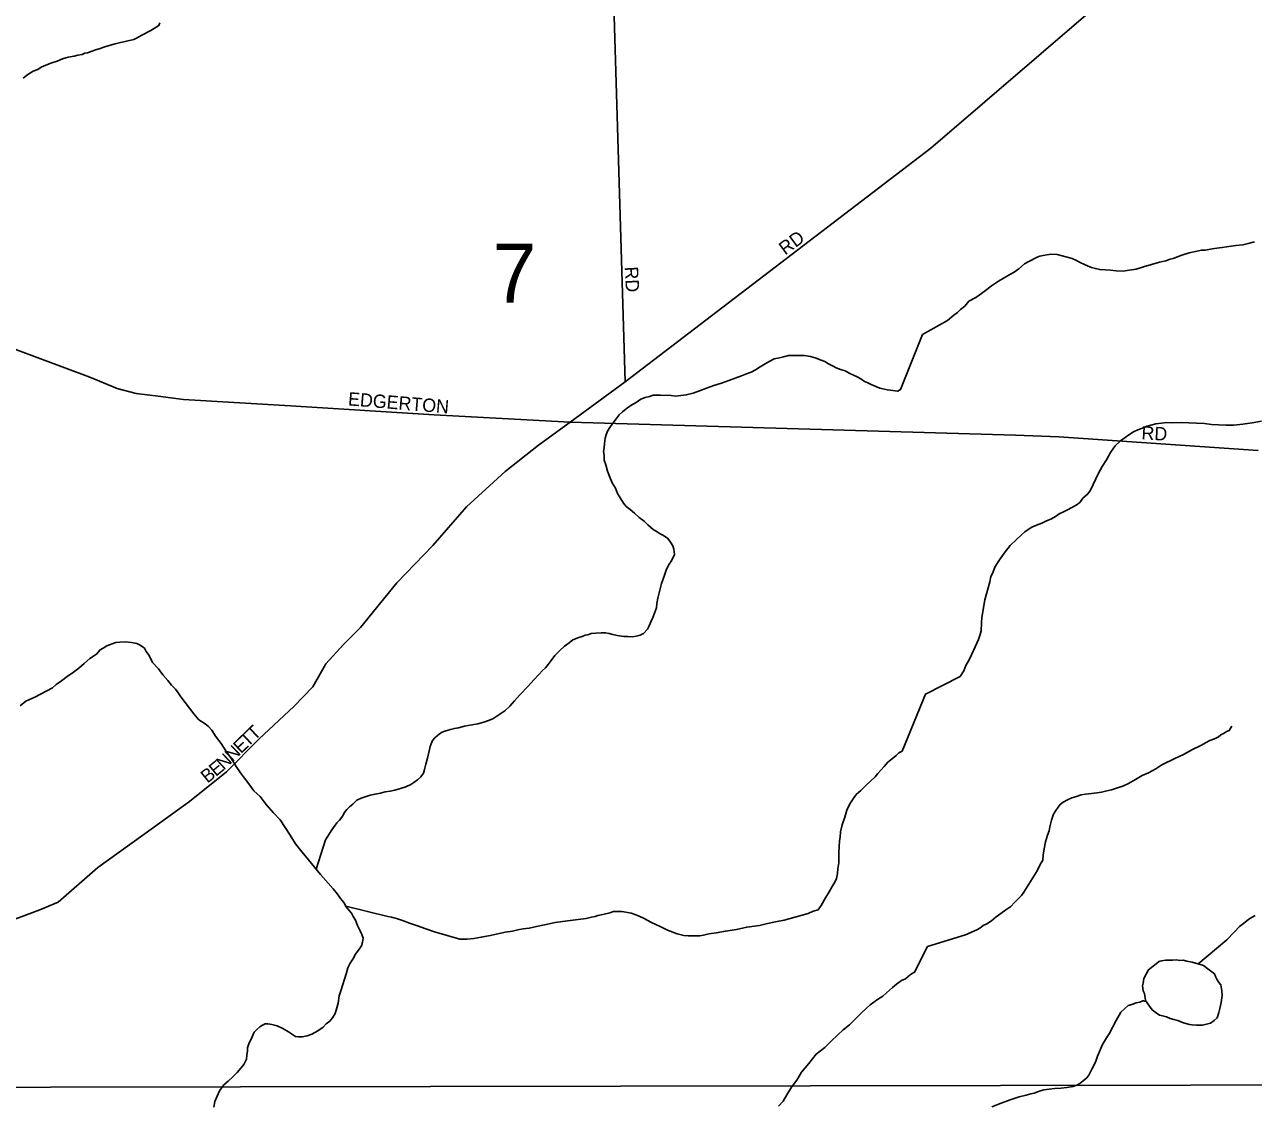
# Model space of a CAD drawing. Extents: x 2010165 to 2382125, y 1060529 to 1407316.
# Drawn here: x 2171324 to 2175929, y 1200051 to 1204103 of the extents above; entities that cross this region are included whole.
import ezdxf

# ---------------------------------------------------------------- set-up
doc = ezdxf.new("R2010")
doc.units = 0
for name, color, linetype in [('GM_X_City_Street', 7, 'Continuous'), ('GM_X_City_Street_Text', 7, 'Continuous'), ('GM_X_Major_River', 7, 'Continuous'), ('GM_X_Minor_Lake', 7, 'Continuous'), ('GM_X_Minor_River', 7, 'Continuous'), ('GM_X_Section', 7, 'Continuous'), ('GM_X_Section_Text', 7, 'Continuous')]:
    doc.layers.add(name, color=color, linetype=linetype)

msp = doc.modelspace()

# ---------------------------------------------------------------- linework, layer by layer
at = {"layer": 'GM_X_City_Street'}
for points in [[(2173574, 1202764.3), (2173532.3, 1204175.7), (2173532.3, 1204459.6), (2173524.5, 1204613.2), (2173495.9, 1204790.3), (2173352.6, 1205368.4), (2173222.5, 1206808.5), (2173149.5, 1207454.3), (2173123.6, 1207698), (2173122.4, 1207710.9)], [(2171215.6, 1200722.6), (2171381.1, 1200784.3), (2171448.9, 1200813), (2171597.8, 1200942.7), (2171806.5, 1201093.1), (2171941.7, 1201190.6), (2172080.7, 1201302.3), (2172201.7, 1201423.7), (2172334.6, 1201547.3), (2172404, 1201620.2), (2172453.3, 1201706.9), (2172518.7, 1201779.7), (2172582.1, 1201842.4), (2172718.7, 1202010.2), (2172853.5, 1202149.8), (2172980.3, 1202295.4), (2173125.2, 1202427.2), (2173250.3, 1202526.6), (2173368.3, 1202613.2), (2173574, 1202764.3), (2174719.8, 1203639.3), (2175335.6, 1204168.8)], [(2171286.8, 1202885.8), (2171567.6, 1202780.9), (2171670.8, 1202738.6), (2171741.9, 1202720), (2171824.8, 1202709.9), (2171919.5, 1202698), (2172320.4, 1202674.3), (2172858.3, 1202640.5), (2173368.3, 1202613.2), (2175037.1, 1202564.4), (2175199.5, 1202557.6), (2175947.2, 1202506.8)]]:
    msp.add_lwpolyline(points, dxfattribs=at)
at = {"layer": 'GM_X_Major_River'}
for points in [[(2171546.9, 1201708.3), (2171568.7, 1201726.6), (2171592.6, 1201743), (2171606.4, 1201759.2), (2171618.3, 1201765.4), (2171632.2, 1201773.6), (2171652.2, 1201781.8), (2171666.1, 1201786), (2171680.1, 1201788.2), (2171700.1, 1201788.5), (2171724.2, 1201786.7), (2171744.3, 1201783), (2171756.4, 1201777.1), (2171772.6, 1201765.3), (2171778.8, 1201753.3), (2171791, 1201737.4), (2171803.3, 1201711.5), (2171825.7, 1201687.7), (2171842, 1201665.8), (2171860.3, 1201643.9), (2171874.6, 1201626.1), (2171888.8, 1201612.2), (2171899, 1201598.3), (2171909.2, 1201582.3), (2171958.1, 1201518.8), (2171976.4, 1201496.9), (2172000.7, 1201481.1), (2172012.8, 1201471.3), (2172025, 1201457.4), (2172039.3, 1201435.5), (2172059.8, 1201407.6), (2172078.1, 1201379.8), (2172098.6, 1201349.9), (2172117, 1201322.1), (2172133.3, 1201298.2), (2172147.6, 1201278.3), (2172163.9, 1201256.4), (2172182.3, 1201230.6), (2172206.6, 1201208.8), (2172229, 1201179), (2172255.5, 1201149.2), (2172281.9, 1201121.4), (2172300.3, 1201093.6), (2172318.7, 1201063.7), (2172339.1, 1201031.8), (2172363.6, 1201000.1), (2172388, 1200972.2), (2172410.4, 1200944.4), (2172432.8, 1200916.6), (2172461.3, 1200884.9), (2172479.6, 1200863), (2172495.9, 1200843.2), (2172508.1, 1200827.3), (2172520.3, 1200811.4), (2172528.5, 1200795.4), (2172540.7, 1200781.5), (2172548.9, 1200771.6), (2172555.1, 1200759.6), (2172563.3, 1200745.7), (2172571.5, 1200725.7), (2172581.8, 1200705.8), (2172588, 1200691.8), (2172592.2, 1200677.8), (2172590.4, 1200663.7), (2172586.6, 1200649.6), (2172574.7, 1200633.5), (2172562.9, 1200617.3), (2172557.1, 1200605.1), (2172551.2, 1200595.1), (2172543.3, 1200584.9), (2172535.5, 1200566.8), (2172529.8, 1200548.6), (2172508.6, 1200480.2), (2172502.9, 1200462), (2172499.2, 1200433.9), (2172491.5, 1200407.7), (2172487.7, 1200395.6), (2172477.9, 1200379.5), (2172468, 1200367.3), (2172454.1, 1200357.1), (2172442.3, 1200344.9), (2172422.4, 1200330.6), (2172400.6, 1200318.3), (2172382.6, 1200312.1), (2172364.6, 1200307.8), (2172350.6, 1200307.7), (2172338.6, 1200309.5), (2172312.3, 1200327.3), (2172292.1, 1200339.1), (2172269.9, 1200348.8), (2172249.8, 1200354.6), (2172235.8, 1200356.4), (2172225.8, 1200356.3), (2172215.8, 1200352.2), (2172205.9, 1200346), (2172194, 1200335.9), (2172184.1, 1200325.7), (2172176.3, 1200307.6), (2172164.6, 1200281.3), (2172158.8, 1200267.2), (2172159, 1200255.2)], [(2171306.6, 1201548.9), (2171328.4, 1201567.2), (2171362.3, 1201581.7), (2171427.9, 1201616.6), (2171441.8, 1201628.8), (2171461.6, 1201643.1), (2171483.5, 1201659.4), (2171507.3, 1201675.7), (2171527.1, 1201690), (2171546.9, 1201708.3)], [(2172159, 1200255.2), (2172157.2, 1200239.1), (2172155.3, 1200225), (2172145.6, 1200204.9), (2172133.8, 1200190.7), (2172119.9, 1200174.4), (2172104.1, 1200158.2), (2172086.3, 1200141.9), (2172070.5, 1200127.7), (2172054.7, 1200105.4), (2172045, 1200085.2), (2172037.2, 1200065.1), (2172033.5, 1200045)]]:
    msp.add_lwpolyline(points, dxfattribs=at)
at = {"layer": 'GM_X_Minor_Lake'}
msp.add_lwpolyline([(2175574, 1200590.8), (2175585.4, 1200593.1), (2175599.4, 1200595.4), (2175613.4, 1200595.8), (2175625.5, 1200596.1), (2175641.5, 1200596.5), (2175653.6, 1200594.8), (2175665.6, 1200595.2), (2175679.7, 1200591.5), (2175699.9, 1200588), (2175712, 1200584.3), (2175726.1, 1200580.7), (2175742.3, 1200575.1), (2175758.7, 1200563.5), (2175773, 1200551.8), (2175783.3, 1200544.1), (2175787.6, 1200534.1), (2175793.9, 1200522.2), (2175800.2, 1200512.4), (2175806.5, 1200502.5), (2175811.1, 1200480.5), (2175811.6, 1200462.5), (2175808.3, 1200436.3), (2175802.8, 1200414.1), (2175799.2, 1200399.9), (2175793.7, 1200379.7), (2175782, 1200369.3), (2175768.2, 1200358.9), (2175758.3, 1200356.7), (2175748.3, 1200354.4), (2175738.3, 1200352.1), (2175728.3, 1200351.8), (2175716.3, 1200351.5), (2175700.2, 1200353.1), (2175690.1, 1200354.9), (2175676, 1200358.5), (2175663.9, 1200362.2), (2175645.6, 1200369.8), (2175631.5, 1200373.4), (2175617.3, 1200377), (2175603.2, 1200382.7), (2175589, 1200386.3), (2175576.9, 1200390), (2175564.7, 1200397.7), (2175550.3, 1200409.4), (2175539.9, 1200423.2), (2175525.3, 1200444.9), (2175523, 1200454.9), (2175520.6, 1200470.9), (2175516.3, 1200480.8), (2175513.8, 1200498.8), (2175515.5, 1200508.9), (2175519, 1200527.1), (2175528.6, 1200545.4), (2175536.2, 1200559.6), (2175577.2, 1200591.4)], dxfattribs=at)
at = {"layer": 'GM_X_Minor_River'}
for points in [[(2171317.9, 1203902.4), (2171335.7, 1203916.7), (2171355.6, 1203928.9), (2171373.5, 1203935.2), (2171385.4, 1203943.3), (2171403.4, 1203951.6), (2171425.3, 1203959.9), (2171445.2, 1203966.1), (2171465.2, 1203974.4), (2171487.1, 1203980.7), (2171509.1, 1203985), (2171523.1, 1203989.2), (2171539.1, 1203991.4), (2171549, 1203995.5), (2171559, 1203997.6), (2171577, 1204003.9), (2171588.9, 1204008), (2171602.9, 1204012.2), (2171620.9, 1204018.5), (2171640.8, 1204024.7), (2171662.8, 1204031), (2171678.7, 1204035.2), (2171732.7, 1204047.9), (2171742.6, 1204052.1), (2171760.5, 1204062.3), (2171772.5, 1204068.5), (2171784.4, 1204074.6), (2171796.4, 1204080.8), (2171806.3, 1204086.9), (2171816.2, 1204093.1), (2171826.2, 1204099.2), (2171830, 1204109.3)], [(2174689.2, 1202941.2), (2174782.7, 1202993.4), (2174806.2, 1203014.1), (2174819.9, 1203024.4), (2174831.7, 1203034.8), (2174847.4, 1203047.3), (2174862.9, 1203065.7), (2174888.6, 1203080.5), (2174910.3, 1203095.1), (2174929.9, 1203109.7), (2174947.6, 1203124.2), (2174973.2, 1203140.9), (2174994.9, 1203153.5), (2175016.6, 1203166.2), (2175032.5, 1203174.6), (2175050.2, 1203187.1), (2175071.7, 1203205.8), (2175085.5, 1203214.1), (2175097.4, 1203220.5), (2175109.3, 1203226.8), (2175119.2, 1203231.1), (2175129.1, 1203235.4), (2175141, 1203237.7), (2175155, 1203240.1), (2175173, 1203242.6), (2175193.1, 1203241.1), (2175249.6, 1203226.5), (2175265.9, 1203218.9), (2175280.1, 1203211.2), (2175296.4, 1203203.6), (2175310.5, 1203198), (2175322.7, 1203192.3), (2175336.9, 1203188.6), (2175353, 1203185), (2175373.1, 1203183.6), (2175393.2, 1203182.1), (2175415.3, 1203180.6), (2175441.4, 1203179.3), (2175463.4, 1203181.9), (2175489.3, 1203186.6), (2175517.2, 1203195.4), (2175547, 1203204.2), (2175576.8, 1203213), (2175600.8, 1203217.6), (2175616.6, 1203224.1), (2175628.6, 1203226.4), (2175644.5, 1203232.9), (2175660.4, 1203239.3), (2175688.2, 1203248.1), (2175712.1, 1203252.7), (2175734.1, 1203257.3), (2175750.1, 1203257.7), (2175762.1, 1203260), (2175774, 1203262.4), (2175792, 1203264.8), (2175812, 1203267.4), (2175828, 1203269.8), (2175846, 1203272.3), (2175863.9, 1203274.8), (2175889.9, 1203277.4), (2175909.9, 1203282), (2175933.7, 1203288.6)], [(2173718.4, 1202188.3), (2173706.3, 1202194.2), (2173694.2, 1202202.1), (2173680.1, 1202209.9), (2173659.8, 1202227.7), (2173645.6, 1202241.6), (2173627.4, 1202255.4), (2173609.1, 1202271.3), (2173592.9, 1202285.1), (2173578.8, 1202297), (2173568.6, 1202308.9), (2173558.4, 1202324.8), (2173546.1, 1202344.7), (2173537.8, 1202364.7), (2173525.5, 1202384.6), (2173517.2, 1202406.6), (2173508.9, 1202428.5), (2173502.6, 1202452.5), (2173496.3, 1202470.5), (2173496.1, 1202488.6), (2173493.9, 1202502.6), (2173495.7, 1202516.6), (2173497.5, 1202532.7), (2173499.3, 1202552.8), (2173503.1, 1202564.9), (2173508.9, 1202579), (2173516.8, 1202593.1), (2173528.6, 1202609.3), (2173540.4, 1202625.5), (2173552.2, 1202639.7), (2173564.1, 1202651.9), (2173578, 1202662.1), (2173587.9, 1202670.2), (2173601.8, 1202678.4), (2173615.7, 1202686.6), (2173633.6, 1202698.9), (2173649.5, 1202705.1), (2173665.5, 1202709.3), (2173679.5, 1202713.5), (2173691.5, 1202713.7), (2173707.5, 1202713.8), (2173747.6, 1202712.3), (2173763.7, 1202710.5), (2173783.7, 1202712.8), (2173803.7, 1202715), (2173829.6, 1202721.4), (2173853.6, 1202729.7), (2173879.5, 1202740), (2173907.4, 1202750.4), (2173935.3, 1202758.8), (2173963.3, 1202769.1), (2173987.2, 1202777.5), (2174011.1, 1202785.8), (2174029, 1202794), (2174047, 1202800.3), (2174062.9, 1202808.5), (2174080.8, 1202820.7), (2174098.7, 1202831), (2174116.6, 1202841.2), (2174132.5, 1202849.5), (2174152.5, 1202853.7), (2174168.4, 1202857.9), (2174186.4, 1202862.2), (2174204.4, 1202862.4), (2174224.5, 1202862.6), (2174246.5, 1202862.9), (2174268.6, 1202859.1), (2174286.7, 1202853.4), (2174308.8, 1202845.6), (2174322.9, 1202839.8), (2174337.1, 1202831.9), (2174351.2, 1202824), (2174365.3, 1202816.2), (2174381.4, 1202810.4), (2174399.5, 1202804.6), (2174413.7, 1202796.7), (2174429.8, 1202788.9), (2174443.9, 1202783.1), (2174458, 1202775.2), (2174472.2, 1202765.3), (2174484.3, 1202759.5), (2174496.4, 1202753.6), (2174514.5, 1202745.8), (2174528.6, 1202739.9), (2174546.7, 1202736.2), (2174556.7, 1202734.3), (2174568.8, 1202732.4), (2174594.9, 1202728.7), (2174596.9, 1202728.7), (2174606.8, 1202734.9), (2174689.2, 1202941.2)], [(2174700.4, 1201593.4), (2174830.7, 1201659.4), (2174844.2, 1201679.9), (2174851.7, 1201700.2), (2174865.1, 1201724.6), (2174880.2, 1201757.1), (2174899.2, 1201797.8), (2174904.7, 1201816), (2174908.3, 1201830.1), (2174909.5, 1201860.3), (2174911, 1201880.4), (2174923.2, 1201947), (2174941.5, 1202013.7), (2174945, 1202033.9), (2174952.6, 1202048.1), (2174960.1, 1202068.4), (2174975.4, 1202092.9), (2174994.7, 1202121.6), (2175018, 1202150.3), (2175041.5, 1202173), (2175059.1, 1202189.5), (2175072.8, 1202201.9), (2175084.6, 1202210.2), (2175098.4, 1202218.6), (2175116.2, 1202227.1), (2175136.1, 1202233.7), (2175153.9, 1202242.2), (2175169.8, 1202248.6), (2175181.6, 1202254.9), (2175191.5, 1202261.2), (2175201.3, 1202269.5), (2175217.2, 1202276), (2175233, 1202284.4), (2175248.8, 1202292.9), (2175264.6, 1202301.3), (2175278.4, 1202311.7), (2175289.9, 1202328.1), (2175307.6, 1202342.6), (2175317.3, 1202354.9), (2175349.5, 1202424), (2175362.9, 1202446.4), (2175378.3, 1202470.9), (2175393.6, 1202499.5), (2175411, 1202524), (2175430.5, 1202542.6), (2175448.2, 1202555.1), (2175462, 1202565.5), (2175479.8, 1202576), (2175495.6, 1202584.5), (2175509.5, 1202588.8), (2175519.4, 1202593.1), (2175529.3, 1202597.4), (2175545.2, 1202601.8), (2175563.2, 1202606.3), (2175585.2, 1202608.9), (2175605.1, 1202611.4), (2175625.2, 1202609.9), (2175659.3, 1202610.8), (2175687.4, 1202609.6), (2175715.5, 1202608.3), (2175745.6, 1202607.1), (2175771.8, 1202603.8), (2175797.9, 1202602.4), (2175826, 1202601.2), (2175856, 1202602), (2175890.1, 1202604.9), (2175924, 1202609.8), (2175959.9, 1202616.8)], [(2172416.4, 1200936.9), (2172451.1, 1201047.3), (2172474.7, 1201083.7), (2172494.4, 1201110), (2172504.3, 1201120.1), (2172516.1, 1201136.3), (2172521.9, 1201148.4), (2172531.8, 1201160.6), (2172541.7, 1201170.8), (2172553.6, 1201180.9), (2172569.4, 1201195.2), (2172585.3, 1201203.4), (2172603.3, 1201209.6), (2172619.2, 1201213.8), (2172637.2, 1201218.1), (2172657.2, 1201222.3), (2172675.2, 1201226.6), (2172693.2, 1201228.8), (2172711.1, 1201233), (2172733.1, 1201239.3), (2172753.1, 1201245.6), (2172771, 1201253.8), (2172782.9, 1201262), (2172796.8, 1201272.2), (2172808.7, 1201282.4), (2172818.5, 1201296.5), (2172822.3, 1201310.6), (2172828.1, 1201330.8), (2172833.8, 1201352.9), (2172837.6, 1201369), (2172841.4, 1201385.1), (2172843.2, 1201397.1), (2172847.1, 1201407.2), (2172853, 1201419.3), (2172860.8, 1201429.5), (2172878.7, 1201443.7), (2172888.6, 1201449.9), (2172898.6, 1201454), (2172910.6, 1201458.2), (2172920.5, 1201460.3), (2172934.5, 1201464.5), (2172950.5, 1201466.7), (2172972.5, 1201473), (2173000.5, 1201477.3), (2173022.4, 1201481.6), (2173044.4, 1201487.9), (2173062.3, 1201494.1), (2173078.3, 1201500.3), (2173124, 1201531), (2173141.8, 1201547.3), (2173159.6, 1201567.6), (2173179.3, 1201589.9), (2173210.9, 1201622.4), (2173232.6, 1201646.7), (2173250.4, 1201667), (2173264.3, 1201681.2), (2173276.1, 1201691.4), (2173286, 1201703.5), (2173297.8, 1201719.7), (2173311.6, 1201737.9), (2173329.4, 1201756.2), (2173347.2, 1201772.5), (2173365.1, 1201784.8), (2173378.9, 1201797), (2173400.9, 1201805.2), (2173412.8, 1201809.4), (2173424.8, 1201813.6), (2173434.8, 1201815.7), (2173446.8, 1201819.9), (2173464.8, 1201822.1), (2173484.8, 1201822.3), (2173500.8, 1201822.5), (2173514.9, 1201820.7), (2173528.9, 1201816.8), (2173545, 1201813), (2173569.1, 1201809.3), (2173585.1, 1201809.5), (2173601.2, 1201807.7), (2173615.2, 1201809.9), (2173631.1, 1201814.1), (2173643.1, 1201820.3), (2173658.9, 1201836.5), (2173664.8, 1201848.6), (2173672.5, 1201866.8), (2173678.4, 1201880.9), (2173684.2, 1201897), (2173691.9, 1201917.1), (2173693.7, 1201933.2), (2173697.5, 1201953.3), (2173703.1, 1201977.5), (2173710.8, 1202007.7), (2173720.4, 1202035.9), (2173730.1, 1202062.1), (2173739.9, 1202080.3), (2173747.7, 1202092.4), (2173759.4, 1202116.6), (2173757.2, 1202136.6), (2173753, 1202148.6), (2173744.8, 1202162.6), (2173734.6, 1202176.5), (2173718.4, 1202188.3)], [(2172527.1, 1200798.2), (2172685.3, 1200759.2), (2172699.3, 1200757.4), (2172717.4, 1200751.6), (2172739.6, 1200743.8), (2172765.8, 1200734.1), (2172795.9, 1200724.4), (2172828.1, 1200712.8), (2172860.4, 1200701.2), (2172954.9, 1200674.2), (2172980.9, 1200674.5), (2173006.9, 1200676.9), (2173034.9, 1200681.2), (2173068.9, 1200687.7), (2173096.8, 1200694), (2173124.8, 1200700.4), (2173152.8, 1200704.7), (2173172.8, 1200709), (2173192.8, 1200713.2), (2173214.8, 1200715.5), (2173242.7, 1200721.9), (2173272.7, 1200728.3), (2173312.7, 1200736.8), (2173358.7, 1200743.4), (2173398.7, 1200747.9), (2173428.7, 1200752.2), (2173448.6, 1200756.5), (2173462.6, 1200758.7), (2173472.6, 1200762.8), (2173490.6, 1200767.1), (2173516.5, 1200773.4), (2173530.5, 1200777.6), (2173546.5, 1200777.8), (2173562.6, 1200778), (2173576.6, 1200776.1), (2173596.7, 1200772.4), (2173618.8, 1200764.6), (2173643, 1200752.9), (2173673.3, 1200737.2), (2173705.5, 1200721.5), (2173733.8, 1200707.8), (2173770, 1200694.2), (2173794.1, 1200688.5), (2173810.2, 1200686.7), (2173826.2, 1200686.9), (2173840.2, 1200687.1), (2173854.2, 1200687.2), (2173868.2, 1200689.4), (2173888.2, 1200693.7), (2173916.2, 1200698), (2173950.2, 1200704.4), (2173992.2, 1200711), (2174030.1, 1200719.5), (2174078.1, 1200726.1), (2174108.1, 1200732.5), (2174138.1, 1200738.8), (2174170, 1200745.3), (2174259.9, 1200770.4), (2174279.8, 1200778.7), (2174297.7, 1200784.9), (2174309.5, 1200801.1), (2174325.2, 1200829.4), (2174338.9, 1200851.7), (2174350.7, 1200871.9), (2174360.5, 1200888), (2174366.3, 1200902.2), (2174370.1, 1200920.3), (2174371.9, 1200938.3), (2174375.6, 1200960.5), (2174375.3, 1200980.5), (2174375.1, 1201000.6), (2174376.8, 1201020.7), (2174378.5, 1201042.8), (2174380.3, 1201056.8), (2174382.1, 1201076.9), (2174387.7, 1201103.1), (2174397.4, 1201131.3), (2174405.1, 1201157.4), (2174416.8, 1201181.7), (2174428.5, 1201199.9), (2174440.4, 1201216.1), (2174458.2, 1201232.3), (2174476, 1201250.6), (2174493.8, 1201266.9), (2174511.6, 1201283.1), (2174521.5, 1201295.3), (2174533.3, 1201307.5), (2174545.2, 1201321.7), (2174559, 1201337.9), (2174576.8, 1201352.2), (2174590.7, 1201362.4), (2174600.6, 1201372.5), (2174612.5, 1201378.7), (2174700.4, 1201593.3), (2174612.5, 1201378.7)], [(2174849.8, 1200690.8), (2174892.5, 1200709.4), (2174904.4, 1200715.7), (2174916.1, 1200726), (2174930, 1200732.4), (2174947.7, 1200742.9), (2174965.4, 1200757.5), (2174983.1, 1200770), (2175000.8, 1200784.5), (2175020.5, 1200797.1), (2175034.1, 1200811.5), (2175047.8, 1200825.9), (2175059.5, 1200838.2), (2175069.2, 1200850.5), (2175119.1, 1200930.2), (2175130.5, 1200954.6), (2175140.1, 1200970.9), (2175141.6, 1200989), (2175145, 1201013.2), (2175150.3, 1201039.4), (2175157.6, 1201063.7), (2175163.2, 1201079.9), (2175166.8, 1201096.1), (2175168.5, 1201106.1), (2175172.2, 1201120.3), (2175179.6, 1201142.6), (2175189.2, 1201156.9), (2175196.9, 1201169.1), (2175204.7, 1201179.4), (2175216.5, 1201187.7), (2175232.3, 1201196.2), (2175248.1, 1201204.6), (2175266, 1201209.1), (2175283.9, 1201215.6), (2175299.9, 1201218), (2175321.8, 1201220.6), (2175341.8, 1201223.1), (2175359.8, 1201225.6), (2175379.8, 1201230.2), (2175397.7, 1201234.6), (2175419.6, 1201241.2), (2175439.4, 1201247.8), (2175461.2, 1201258.4), (2175486.9, 1201273.1), (2175512.5, 1201287.9), (2175536.3, 1201298.5), (2175564, 1201313.3), (2175585.7, 1201327.9), (2175635.2, 1201351.3), (2175666.8, 1201366.2), (2175700.4, 1201385.2), (2175734.1, 1201402.1), (2175749.9, 1201410.6), (2175765.7, 1201419), (2175783.5, 1201425.5), (2175795.4, 1201431.8), (2175797.4, 1201431.9), (2175807.2, 1201440.2), (2175819.1, 1201446.5), (2175828.9, 1201452.8), (2175838.8, 1201457.1), (2175848.4, 1201473.4)], [(2175720.3, 1200580.2), (2175830, 1200671.8), (2175857.3, 1200700.6), (2175876.8, 1200721.2), (2175892.5, 1200733.6), (2175906.2, 1200744), (2175916, 1200752.3), (2175935.8, 1200762.9)], [(2174849.8, 1200690.8), (2174708.3, 1200646.6)], [(2174149.1, 1200048.8), (2174166.9, 1200067.1), (2174180.6, 1200091.3), (2174198.2, 1200119.6), (2174217.9, 1200145.9), (2174235.6, 1200176.2), (2174263.2, 1200208.7), (2174290.8, 1200243.1), (2174322.5, 1200267.6), (2174346.2, 1200292), (2174370, 1200314.3), (2174391.8, 1200334.6), (2174415.6, 1200353), (2174435.3, 1200373.3), (2174461, 1200399.7), (2174492.7, 1200428.2), (2174520.5, 1200448.6), (2174540.4, 1200460.9), (2174554.2, 1200473.1), (2174576, 1200493.4), (2174591.9, 1200505.6), (2174609.7, 1200519.9), (2174625.7, 1200526.1), (2174635.6, 1200534.3), (2174647.5, 1200544.4), (2174659.4, 1200550.6), (2174708.3, 1200646.6)], [(2174948.5, 1200046.2), (2174984.2, 1200059.2), (2175018, 1200072.1), (2175051.8, 1200083.1), (2175077.7, 1200089.8), (2175095.6, 1200094.3), (2175107.6, 1200096.6), (2175123.4, 1200103), (2175143.3, 1200109.6), (2175163.3, 1200112.1), (2175185.3, 1200114.7), (2175209.3, 1200115.3), (2175229.3, 1200117.9), (2175253.2, 1200122.5), (2175267.2, 1200126.9), (2175279, 1200133.2), (2175290.8, 1200143.6), (2175304.5, 1200154), (2175312.3, 1200164.2), (2175323.7, 1200186.6), (2175331.3, 1200200.9), (2175338.9, 1200217.1), (2175344.4, 1200235.3), (2175363.3, 1200280), (2175378.7, 1200304.5), (2175388.3, 1200318.8), (2175415, 1200369.7), (2175432.2, 1200400.3), (2175459.6, 1200425.1), (2175473.6, 1200429.5), (2175489.4, 1200435.9), (2175503.4, 1200438.3), (2175515.3, 1200442.6), (2175517.3, 1200442.7), (2175525.4, 1200440.9)]]:
    msp.add_lwpolyline(points, dxfattribs=at)
at = {"layer": 'GM_X_Section'}
msp.add_lwpolyline([(2170618.6, 1205608.5), (2176316.2, 1205618.7), (2176405.5, 1200128.5), (2170707.4, 1200117.9)], close=True, dxfattribs=at)

# ---------------------------------------------------------------- texts
at = {"layer": 'GM_X_City_Street_Text'}
for s, rotation, p in [('RD', 36.2589, (2174174, 1203237.1)), ('RD', 273.011, (2173572.8, 1203194.9)), ('EDGERTON', 355.3642, (2172534.6, 1202675.8)), ('RD', 356.9776, (2175508.7, 1202548.2)), ('T', 44.0959, (2172185.3, 1201416.7)), ('E', 44.0781, (2172134.7, 1201367.7)), ('T', 44.0959, (2172160, 1201392.2)), ('N', 44.0499, (2172103.1, 1201337)), ('E', 39.2481, (2172040.1, 1201281.9)), ('N', 42.7305, (2172069.9, 1201306.3)), ('B', 38.7546, (2172008.9, 1201256.8))]:
    msp.add_text(s, height=50, rotation=rotation, dxfattribs=at).set_placement(p)
at = {"layer": 'GM_X_Section_Text'}
msp.add_text('7', height=221, rotation=0, dxfattribs=at).set_placement((2173077.2, 1203061.1))

doc.saveas('drawing.dxf')
